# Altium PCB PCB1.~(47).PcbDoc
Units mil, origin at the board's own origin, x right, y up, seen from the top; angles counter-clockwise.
Board outline 6000 x 4000 mil, 2 copper layers (Top Layer, Bottom Layer); 38 components, 28 nets, 163 pads, 78 vias.
Unrouted connection lines stored in the file: 51.
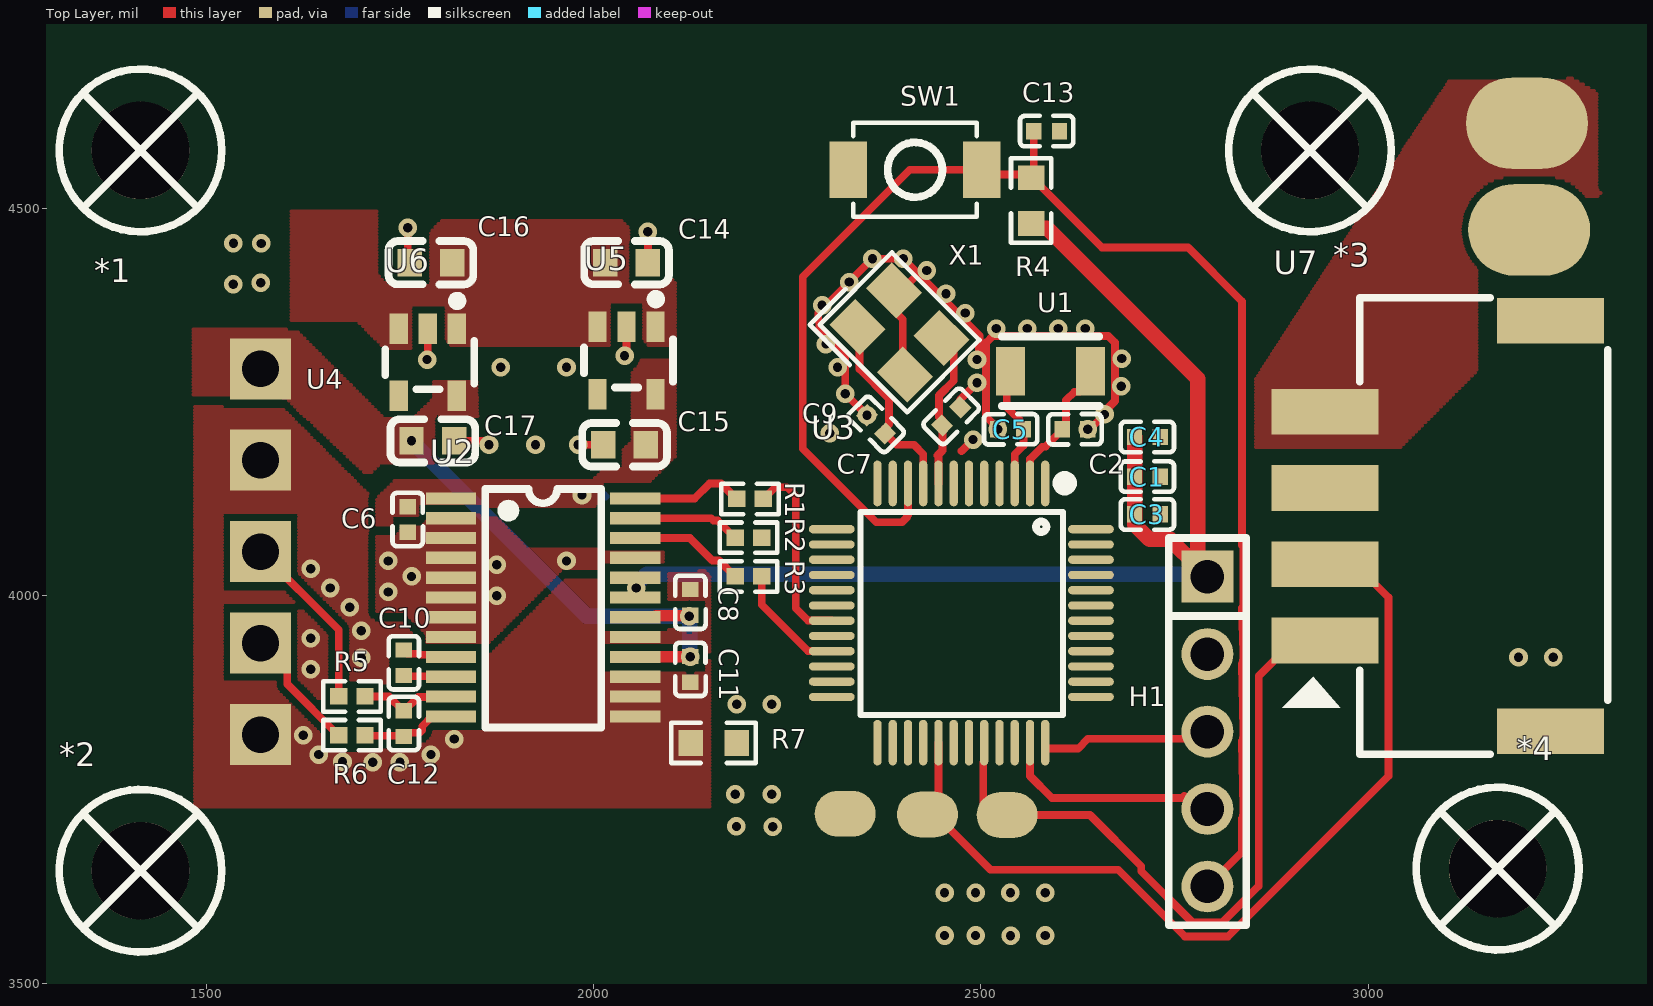
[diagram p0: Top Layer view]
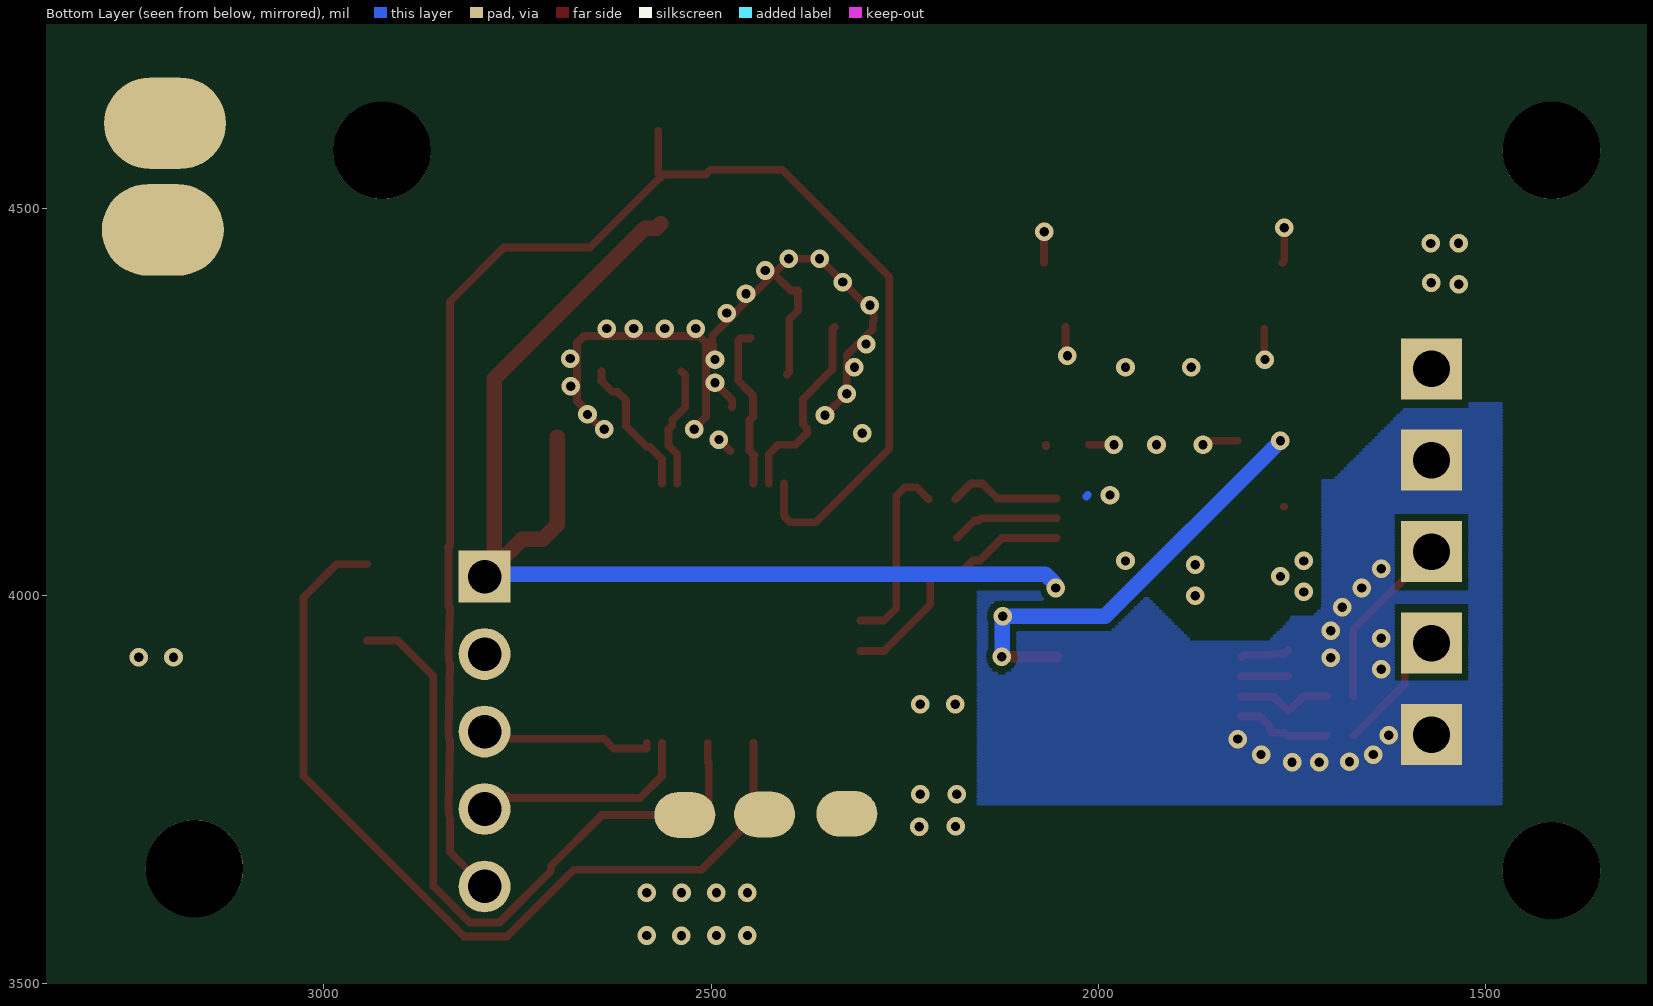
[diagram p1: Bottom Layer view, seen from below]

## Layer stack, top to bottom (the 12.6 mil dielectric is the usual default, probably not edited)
Top Solder: solder mask 0.4, Solder Resist, Dk 3.5
Top Layer: signal copper 1.4
Dielectric 1: dielectric 12.6, FR-4, Dk 4.8
Bottom Layer: signal copper 1.4
Bottom Solder: solder mask 0.4, Solder Resist, Dk 3.5

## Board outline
1000,1000 7000,1000 7000,5000 1000,5000

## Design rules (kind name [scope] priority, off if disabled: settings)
Clearance [All] p1: gap=8 ignorepadtopadclearanceinfootprint=FALSE
ComponentClearance [All] p1: gap=0 collisioncheckmode=3 verticalgap=0 showdistances=FALSE
HoleSize [All] p1: absolutevalues=TRUE maxlimit=130 minlimit=1 maxpercent=80.000 minpercent=20.000
MinimumSolderMaskSliver [All] p1: minsoldermaskwidth=4
PlaneConnect [All] p1: planeconnectstyle=Direct reliefexpansion=20 reliefentries=4 reliefconductorwidth=10 reliefairgap=10
PolygonConnect [All] p1: connectstyle=Direct reliefconductorwidth=10 reliefentries=4 polygonreliefangle="90 Angle" airgapwidth=10
RoutingVias [All] p1: holewidth=28 width=50 viastyle="Through Hole" minholewidth=28 minwidth=50 maxholewidth=28 maxwidth=50
SilkToSilkClearance [All] p1: silktosilkclearance=2
SilkToSolderMaskClearance [IsPad] p1: minsilkscreentomaskgap=2 clearancetoexposedcopper=TRUE
SolderMaskExpansion [All] p1: expansion=0 istentingtop=FALSE
SupplyNets "Schematic Supply Nets_2" [InNet('6V')] p1: voltage=0.000
SupplyNets "Schematic Supply Nets" [InNet('3V3')] p2: voltage=0.000
SupplyNets "Schematic Supply Nets_4" [InNet('5V')] p3: voltage=0.000
SupplyNets "Schematic Supply Nets_3" [InNet('DGND')] p4: voltage=0.000
SupplyNets "Schematic Supply Nets_1" [InNet('AGND')] p5: voltage=0.000
Width [All] p1: maxlimit=50 minlimit=10 preferedwidth=10
24 further rules are at their usual default settings.

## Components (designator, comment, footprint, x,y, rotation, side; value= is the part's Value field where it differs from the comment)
*1 "螺丝孔_1" M3螺丝 1415,4575 r0 top
*2 "螺丝孔_1" M3螺丝 1415,3645 r0 top
*3 "螺丝孔_1" M3螺丝 2925,4575 r0 top
*4 "螺丝孔_1" M3螺丝 3167.2,3647.74 r0 top
C1 "cc0402krx7r7bb104" C0402 2715,4153.83 r0 top value=100nF
C2 "cc0402jrnpo9bn220" C0402 2621.54,4215 r180 top value=22pF
C3 "cc0402krx7r7bb104" C0402 2715,4105 r0 top value=100nF
C4 "cc0402krx7r7bb104" C0402 2715,4205 r180 top value=100nF
C5 "cc0402jrnpo9bn220" C0402 2538.46,4215 r0 top value=22pF
C6 "cc0402krx7r7bb104" C0402 1760,4098.46 r270 top value=100nF
C7 "cc0402jrnpo9bn180" C0402 2461.7,4231.7 r45 top value=18pF
C8 "cc0402krx7r7bb104" C0402 2125,3991.54 r90 top value=100nF
C9 "cc0402jrnpo9bn180" C0402 2364.68,4221.29 r315 top value=18pF
C10 "cc0402krx7r7bb104" C0402 1755,3913.46 r90 top value=100nF
C11 "gcm155r71h103ka55d" C0402 2125,3905 r270 top value=10nF
C12 "gcm155r71h103ka55d" C0402 1755,3835 r270 top value=10nF
C13 "cc0402krx7r7bb104" C0402 2585,4600 r180 top value=100nF
C14 "cga0603x5r105k500jt" C0603 2042.56,4430 r0 top value=1uF
C15 "cga0603x5r105k500jt" C0603 2040,4195 r180 top value=1uF
C16 "cga0603x5r105k500jt" C0603 1790,4430 r180 top value=1uF
C17 "cga0603x5r105k500jt" C0603 1792.44,4200 r0 top value=1uF
H1 "pz254v-11-05p" HDR-TH_5P-P2.54-V-M 2792.56,3824.68 r270 top
R1 "frc0402f47r0ts" R0402 2202.04,4125 r0 top value=47Ω
R2 "frc0402f47r0ts" R0402 2200,4075 r0 top value=47Ω
R3 "frc0402f47r0ts" R0402 2200,4025 r0 top value=47Ω
R4 "frc0603f1002ts" R0603 2565.04,4510.31 r270 top value=10kΩ
R5 "frc0402f1000ts" R0402 1687.96,3870 r0 top value=100Ω
R6 "frc0402f1000ts" R0402 1687.96,3820 r0 top value=100Ω
R7 "0603waf0000t5e" R0603 2155,3810 r0 top value=0Ω
SW1 "ts-1088-ar02016" SW-SMD_L3.9-W3.0-P4.45 2415,4550 r0 top
U1 "fc31m2-32.768-ntlnndtl" CRYSTAL-SMD_L3.2-W1.5 2590,4290 r0 top value=32.768kHz
U2 "ads1232ipwr" TSSOP-24_L7.8-W4.4-P0.65-LS6.4-BL 1935,3985 r270 top
U3 "stm32g031c8t6" LQFP-48_L7.0-W7.0-P0.50-LS9.0-BL 2474.84,3977.68 r180 top
U4 "5个焊盘" 5个焊盘 1570,4293.1 r270 top
U5 "tps7a2033pdbvr" SOT-23-5_L2.9-W1.6-P0.95-LS2.8-BR 2042.56,4303.8 r90 top
U6 "tps7a2050pdbvr" SOT-23-5_L2.9-W1.6-P0.95-LS2.8-BR 1786.01,4301.56 r90 top
U7 "bx-xh2.54-4pwt" CONN-SMD_4P-P2.50_BX-XH2.54-4PWT 3090,4090 r90 top
X1 "x32258mob4si" CRYSTAL-SMD_4P-L3.2-W2.5-BL 2395,4340 r315 top value=8MHz

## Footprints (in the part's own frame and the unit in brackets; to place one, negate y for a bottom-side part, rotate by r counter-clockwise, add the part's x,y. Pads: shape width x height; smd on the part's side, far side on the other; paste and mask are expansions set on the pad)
5个焊盘 [mm]
  rect 2x2 hole 1.2: 1(0,0) 2(3,0) 3(6.001,0) 4(9,0) 5(12,0)
C0402 [mm]
  rect 0.5x0.54 smd: 1(-0.42,0) 2(0.42,0)
  silkscreen extent -0.87,-0.5 0.87,0.5
C0603 [mm]
  rect 0.8x0.9 smd: 1(-0.7,0) 2(0.7,0)
  silkscreen extent -1.39,-0.71 1.39,0.71
CONN-SMD_4P-P2.50_BX-XH2.54-4PWT [mm]
  rect 1.5x3.5 smd paste+0 mask+0.05: 1(-3.75,3.7) 2(-1.25,3.7) 3(1.25,3.7) 4(3.75,3.7) 5(6.73,-3.7) 6(-6.73,-3.7)
  silkscreen extent -7.49,-5.57 7.49,5.1
CRYSTAL-SMD_4P-L3.2-W2.5-BL [mm]
  rect 1.4x1.2 smd: 1(-1.1,-0.85) 2(1.1,-0.85) 3(1.1,0.85) 4(-1.1,0.85)
  silkscreen extent -2.26,-1.91 2.03,1.68
CRYSTAL-SMD_L3.2-W1.5 [mm]
  rect 0.95x1.6 smd: 1(-1.308,0) 2(1.308,0)
  silkscreen extent -1.6,-1.14 1.6,1.14
HDR-TH_5P-P2.54-V-M [mm]
  rect 1.7x1.7 hole 1.1: 1(-5.08,0)
  round 1.7 hole 1.1: 2(-2.54,0) 3(0,0) 4(2.54,0) 5(5.08,0)
  silkscreen extent -6.35,-1.27 6.35,1.27
LQFP-48_L7.0-W7.0-P0.50-LS9.0-BL [mm]
  oval 0.27x1.5 smd paste+0 mask+0.05: 1(-2.75,-4.25) 2(-2.25,-4.25) 3(-1.75,-4.25) 4(-1.25,-4.25) 5(-0.75,-4.25) 6(-0.25,-4.25) 7(0.25,-4.25) 8(0.75,-4.25) 9(1.25,-4.25) 10(1.75,-4.25) 11(2.25,-4.25) 12(2.75,-4.25) 25(2.75,4.25) 26(2.25,4.25) 27(1.75,4.25) 28(1.25,4.25) 29(0.75,4.25) 30(0.25,4.25) 31(-0.25,4.25) 32(-0.75,4.25) 33(-1.25,4.25) 34(-1.75,4.25) 35(-2.25,4.25) 36(-2.75,4.25)
  oval 1.5x0.27 smd paste+0 mask+0.05: 13(4.25,-2.75) 14(4.25,-2.25) 15(4.25,-1.75) 16(4.25,-1.25) 17(4.25,-0.75) 18(4.25,-0.25) 19(4.25,0.25) 20(4.25,0.75) 21(4.25,1.25) 22(4.25,1.75) 23(4.25,2.25) 24(4.25,2.75) 37(-4.25,2.75) 38(-4.25,2.25) 39(-4.25,1.75) 40(-4.25,1.25) 41(-4.25,0.75) 42(-4.25,0.25) 43(-4.25,-0.25) 44(-4.25,-0.75) 45(-4.25,-1.25) 46(-4.25,-1.75) 47(-4.25,-2.25) 48(-4.25,-2.75)
  silkscreen extent -3.59,-4.46 3.3,3.34
M3螺丝 [mil]
  round 126 hole 126 paste-99999 mask+4: 1(0,0)
  silkscreen extent -105,-105 105,105
R0402 [mm]
  rect 0.566x0.54 smd paste-100 mask+0.051: 1(-0.433,0) 2(0.433,0)
  silkscreen extent -0.94,-0.5 0.94,0.5
R0603 [mil]
  rect 31.75x34.02 smd paste-3937.01 mask+2: 1(-29.66,0) 2(29.66,0)
  silkscreen extent -55,-26 55,26
SOT-23-5_L2.9-W1.6-P0.95-LS2.8-BR [mm]
  rect 1x0.6 smd paste+0 mask+0.05: 1(1.1,-0.95) 2(1.1,0) 3(1.1,0.95) 4(-1.1,0.95) 5(-1.1,-0.95)
  silkscreen extent -0.89,-1.52 2.16,1.4
SW-SMD_L3.9-W3.0-P4.45 [mm]
  rect 1.23x1.86 smd: 1(-2.185,0) 2(2.185,0)
  silkscreen extent -2.03,-1.54 2.03,1.54
TSSOP-24_L7.8-W4.4-P0.65-LS6.4-BL [mm]
  rect 0.4x1.65 smd: 1(-3.575,-3.023) 2(-2.925,-3.023) 3(-2.275,-3.023) 4(-1.625,-3.023) 5(-0.975,-3.023) 6(-0.325,-3.023) 7(0.325,-3.023) 8(0.975,-3.023) 9(1.625,-3.023) 10(2.275,-3.023) 11(2.925,-3.023) 12(3.575,-3.023) 13(3.575,3.023) 14(2.925,3.023) 15(2.275,3.023) 16(1.625,3.023) 17(0.975,3.023) 18(0.325,3.023) 19(-0.325,3.023) 20(-0.975,3.023) 21(-1.625,3.023) 22(-2.275,3.023) 23(-2.925,3.023) 24(-3.575,3.023)
  silkscreen extent -3.89,-1.91 3.94,1.9

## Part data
C1 C3 C4 C6 C8 C10 C13: "容值:100nF;精度:±10%;额定电压:16V;温度系数:X7R;", JLCPCB Part Class="Extended Part", LCSC Part Name="100nF ±10% 16V", Manufacturer=YAGEO(国巨), ManufacturerPart=CC0402KRX7R7BB104, Temperature Coefficient=X7R, Tolerance=±10%, Voltage Rating=16V
C2 C5: "容值:22pF;精度:±5%;额定电压:50V;温度系数:NP0;", JLCPCB Part Class="Extended Part", LCSC Part Name="22pF ±5% 50V", Manufacturer=YAGEO(国巨), ManufacturerPart=CC0402JRNPO9BN220, Temperature Coefficient=NP0, Tolerance=±5%, Voltage Rating=50V
C7 C9: "容值:18pF;精度:±5%;额定电压:50V;温度系数:NP0;", JLCPCB Part Class="Extended Part", LCSC Part Name="18pF ±5% 50V", Manufacturer=YAGEO(国巨), ManufacturerPart=CC0402JRNPO9BN180, Temperature Coefficient=NP0, Tolerance=±5%, Voltage Rating=50V
C11 C12: "容值:10nF;精度:±10%;额定电压:50V;温度系数:X7R;", JLCPCB Part Class="Extended Part", LCSC Part Name="10nF ±10% 50V", Manufacturer=muRata(村田), ManufacturerPart=GCM155R71H103KA55D, Temperature Coefficient=X7R, Tolerance=±10%, Voltage Rating=50V
C14 C15 C16 C17: "容值:1uF;精度:±10%;额定电压:50V;温度系数:X5R;", JLCPCB Part Class="Extended Part", LCSC Part Name="1uF ±10% 50V 停产", Manufacturer=HRE(芯声), ManufacturerPart=CGA0603X5R105K500JT, Temperature Coefficient=X5R, Tolerance=±10%, Voltage Rating=50V
H1: "插针结构:1x5P;间距:2.54mm;行距:-;圆针/方针:方针;安装方式:直插;排数:单排;总PIN位数:5P;额定电流:3A;额定电压:250V;配合针长度:6mm;塑高:2.5mm;端接针长度:3mm;触头材质:黄铜;触头镀层:-;工作温度:-40℃~+105℃;颜色:黑色;", Color=黑色, Current Rating=3A, JLCPCB Part Class="Extended Part", LCSC Part Name="1x5P 间距:2.54mm 方针 直插", Manufacturer=XFCN(兴飞), ManufacturerPart=PZ254V-11-05P, Operating Temperature=-40℃~+105℃, Voltage Rating (Max)=250V
R1 R2 R3: "电阻类型:厚膜电阻;阻值:47Ω;精度:±1%;功率:62.5mW;工作电压:50V;温度系数:±100ppm/℃;", JLCPCB Part Class="Extended Part", LCSC Part Name="47Ω ±1% 62.5mW 厚膜电阻", Manufacturer=FOJAN(富捷), ManufacturerPart=FRC0402F47R0TS, Operating Temperature=-55℃~+155℃, Power(Watts)=62.5mW, Temperature Coefficient=±100ppm/℃, Tolerance=±1%, Voltage-Supply(Max)=50V
R4: "电阻类型:厚膜电阻;阻值:10kΩ;精度:±1%;功率:100mW;工作电压:75V;温度系数:±100ppm/℃;", JLCPCB Part Class="Extended Part", LCSC Part Name="10kΩ ±1% 100mW 厚膜电阻", Manufacturer=FOJAN(富捷), ManufacturerPart=FRC0603F1002TS, Operating Temperature=-55℃~+155℃, Power(Watts)=100mW, Temperature Coefficient=±100ppm/℃, Tolerance=±1%, Voltage-Supply(Max)=75V
R5 R6: "电阻类型:厚膜电阻;阻值:100Ω;精度:±1%;功率:62.5mW;工作电压:50V;温度系数:±100ppm/℃;", JLCPCB Part Class="Extended Part", LCSC Part Name="100Ω ±1% 62.5mW 厚膜电阻", Manufacturer=FOJAN(富捷), ManufacturerPart=FRC0402F1000TS, Operating Temperature=-55℃~+155℃, Power(Watts)=62.5mW, Temperature Coefficient=±100ppm/℃, Tolerance=±1%, Voltage-Supply(Max)=50V
R7: "电阻类型:厚膜电阻;阻值:0Ω;精度:±1%;功率:100mW;工作电压:75V;温度系数:-;", JLCPCB Part Class="Basic Part", LCSC Part Name="0Ω ±1% 100mW 厚膜电阻", Manufacturer=UNI-ROYAL(厚声), ManufacturerPart=0603WAF0000T5E, Operating Temperature=-55℃~+155℃, Power(Watts)=100mW, Temperature Coefficient=-, Tolerance=±1%, Voltage-Supply(Max)=75V
SW1: "电路结构:单刀单掷;按钮形状:圆形按钮;作用力:1.6N;安装方式:立贴;开关长度:3.9mm;开关宽度:3mm;开关高度:2mm;带支架:不带支架;触点电流:50mA;额定电压:12V;带灯:-;工作寿命:10万次;", Actuator/Cap Color=黑色, Contact Current=50mA, IP Rating=-, JLCPCB Part Class="Basic Part", LCSC Part Name="3.9*3*2mm 立贴 轻触开关", Manufacturer=XUNPU(讯普), ManufacturerPart=TS-1088-AR02016, Operating Force=1.6N, Operating Temperature=-30℃~+80℃, Voltage Rating=12V
U1: "晶振类型:贴片晶振;频率:32.768kHz;常温频差:±10ppm;负载电容:12.5pF;频率稳定度:±10ppm;", Equivalent Series Resistance(ESR)=70kΩ, Frequency Stability=±10ppm, JLCPCB Part Class="Extended Part", LCSC Part Name="3215 2P 32.768kHz 12.5pF ±10ppm -40~+85℃(±10ppm)", Load Capacitance=12.5pF, Manufacturer=HCI(杭晶), ManufacturerPart=FC31M2-32.768-NTLNNDTL, Operating Temperature=-40℃~+85℃
U2: "分辨率(位):24;采样率:10Hz;工作电压:2.7V~5.3V;接口类型:SPI;", Clock Frequency=4.9152MHz；200kHz~8MHz, JLCPCB Part Class="Extended Part", LCSC Part Name="用于桥式传感器的24bit 模数转换器", Manufacturer=TI(德州仪器), ManufacturerPart=ADS1232IPWR, Operating Temperature=-40℃~+105℃, Quiescent Current (Iq)=1.3uA, Temperature Sensors=内置, Voltage - Supply=2.7V~5.3V, Voltage Reference=外置, Voltage Reference Drift=-
U3: "CPU内核:ARM Cortex-M0+;CPU最大主频:64MHz;CPU位数:32 Bit;", JLCPCB Part Class="Extended Part", LCSC Part Name="主流Arm Cortex-M0+ MCU，具有64 KB Flash存储器、8 KB RAM、64 MHz CPU、2x USART、定时器、ADC和通信接口，1.7-3.6V", Manufacturer=ST(意法半导体), ManufacturerPart=STM32G031C8T6, Operating Temperature=-40℃~+85℃, Voltage - Supply=1.7V~3.6V
U5: "输出类型:固定;最大输入电压:6V;输出电压:3.3V;输出电流:300mA;输出极性:正极;", Dropout Voltage=140mV@(300mA), JLCPCB Part Class="Extended Part", LCSC Part Name="具有高 PSRR 的 300mA、超低噪声、低 IQ、低压降 (LDO) 线性稳压器", Manufacturer=TI(德州仪器), ManufacturerPart=TPS7A2033PDBVR, Maximum Input Voltage=6V, Operating Temperature=-40℃~+125℃@(Tj), Output Current=300mA, Output Voltage=3.3V, standby current=15uA
U6: "输出极性:正极;工作电压:6V;输出电压:5V;输出电流:300mA;电源纹波抑制比(PSRR):65dB@(100Hz);输出类型:固定;", JLCPCB Part Class="Extended Part", LCSC Part Name="800mV~5.5V 300mA 6V", Manufacturer=TI(德州仪器), ManufacturerPart=TPS7A2050PDBVR, Operating Temperature=-40℃~+125℃@(Tj), Output Current=300mA, Output Voltage=5V, Power Supply Rejection Ratio (PSRR)=65dB@(100Hz), standby current=6.5uA, Voltage - Supply=6V, Voltage Dropout=140mV@(300mA)
U7: "插针结构:1x4P;间距:2.5mm;安装方式:卧贴;参考系列:XH;总PIN数:4P;排数:1;每排PIN数:4;行距:-;额定电流:3A;触头材质:黄铜;触头镀层:锡;工作温度:-25℃~+85℃;", Color=米色, Current Rating=3A, Flame Retardant Rating=-, JLCPCB Part Class="Extended Part", LCSC Part Name="1x4P 间距:2.5mm 卧贴 系列:XH", Manufacturer=Bossie(博锡), ManufacturerPart=BX-XH2.54-4PWT, Operating Temperature=-25℃~+85℃, Voltage Rating=250V
X1: "晶振类型:贴片晶振;频率:8MHz;常温频差:±10ppm;负载电容:12pF;频率稳定度:±20ppm;", Equivalent Series Resistance(ESR)=180Ω, Frequency Stability=±20ppm, JLCPCB Part Class="Extended Part", LCSC Part Name="YSX321SL 8MHZ 4P 3225 12PF ±10PPM -40~85℃ (±20PPM)", Load Capacitance=12pF, Manufacturer=YXC(扬兴晶振), ManufacturerPart=X32258MOB4SI, Normal temperature Frequency Tolerance=±10ppm, Operating Temperature=-40℃~+85℃

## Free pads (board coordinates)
  oval 78.74x59.06 all layers, no hole: 7(2324.75,3718.52) 7(2431.17,3717.65) 7(2533.87,3716.95)
  oval 157.48x118.11 all layers, no hole: 7(3205,4610) 7(3208.05,4472.38)

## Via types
v1: diameter 24, hole 12, Top Layer to Bottom Layer, tented both sides, 78 vias

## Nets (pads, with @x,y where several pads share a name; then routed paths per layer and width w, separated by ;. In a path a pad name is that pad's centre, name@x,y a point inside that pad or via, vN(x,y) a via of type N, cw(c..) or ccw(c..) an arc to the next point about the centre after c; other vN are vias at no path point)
3V3: C1.1 C3.1 C4.2 C6.1 C15.1 H1.1 R4.2 U2.1 U2.19 U2.20 U3.4 U3.5 U3.6 U5.5 | length 1532.9
  Top Layer w10: C6.1 C6.1@1760.79,4115 ; C15.1@2067.56,4193.03 C15.1
  Top Layer w20: R4.2 2570.92,4474.77 2585.41,4474.77 2780.25,4279.94 H1.1@2780.25,4036.99 ; C4.2@2698.46,4204.53 C4.2 C3.1 2698.62,4104.84 2698.62,4091.99 2717.84,4072.77 2744.47,4072.77 H1.1@2780.25,4036.99 ; H1.1 H1.1@2780.25,4036.99
  Bottom Layer w10: v1@1983.6,4128.6 v1(1985,4130) ; 2013.74,4130 2015.53,4128.21
  Bottom Layer w20: v1(2055,4010) 2055.77,4010.77 2055.77,4015.1 2068.72,4028.05 2789.19,4028.05 H1.1
5V: C8.1 C11.1 C17.1 U2.16 U2.18 U4.1 U6.5 | length 649.2
  Top Layer w10: v1(2123.61,3973.61) C8.1 ; v1(2124.74,3921.28) C11.1
  Top Layer w15: U2.16 2054.26,3921.28 v1(2124.74,3921.28) ; U2.18 2078.61,3972.21 2080.81,3974.42 2122.79,3974.42 v1(2123.61,3973.61)
  Bottom Layer w10: v1(2123.61,3973.61) v1@2124.17,3973.04 ; v1@2124.17,3921.85 v1(2124.74,3921.28)
  Bottom Layer w20: v1(1765,4200) 1991.39,3973.61 v1(2123.61,3973.61) ; v1@2124.17,3921.85 v1@2124.17,3973.04
6V: C14.1 C16.1 pad.7@3205,4610 U5.1 U5.3 U6.1 U6.3 U7.4
AGND: C8.2 C11.2 R7.1 U2.13 U2.14 U2.15 U2.17 U4.2 U4.5
  other v1: 1715,3785 1750,3785 1675.87,3785.63 1645,3795 1790,3795 1820,3815 1625,3820 1635,3905 1700,3920 1635,3945 1700,3955 1685,3985 1660,4010 1635,4035
AINN1: R6.1 U4.4 | length 160.9
  Top Layer w10: U4.4 1604.37,3904.39 1604.37,3886.04 1670.41,3820 R6.1
AINP1: R5.1 U4.3 | length 228.7
  Top Layer w10: U4.3 1670.92,3955.94 R5.1
DGND: C1.2 C2.1 C3.2 C4.1 C5.1 C6.2 C7.2 C9.1 C13.1 C14.2 C15.2 C16.2 C17.2 H1.2 pad.7@2324.75,3718.52 pad.7@3208.05,4472.38 R7.2 SW1.1 U2.2 U2.3 U2.4 U2.5 U2.6 U2.7 U2.8 U2.21 U3.7 U5.2 U6.2 U7.3 U7.5 U7.6 X1.2 X1.4 | length 1352.5
  Top Layer w10: v1(1760,4475) 1760,4432.44 C16.2 ; v1(1785,4305) 1786.02,4306.02 U6.2 ; C17.2 1856.21,4200 1861.21,4195 v1(1865,4195) ; v1(1980,4195) C15.2 ; v1(2040,4310) 2042.57,4312.56 U5.2 ; v1(2070,4470) 2070.12,4469.88 C14.2 ; v1(2352.98,4232.98) v1(2325,4260.96) 2325,4310.88 2291.52,4344.36 2291.52,4353.48 2290,4355 2290,4365 v1(2360,4435) v1(2400,4435) v1@2419.14,4415.86 ; X1.2 2399.18,4288.5 2399.18,4356.81 2388.04,4367.95 X1.4 2397.57,4394.29 v1@2419.14,4415.86 ; C7.2 2472.83,4243.95 2472.83,4250.8 2473.39,4251.35 2473.39,4253.39 v1(2495,4275) ; v1(2495,4305) 2497.68,4307.68 2497.68,4324.07 2498.48,4324.87 2498.48,4335.64 2467.06,4367.06 2467.06,4367.94 v1@2419.14,4415.86 ; v1(2521.92,4215) 2521.92,4215.79 2506.8,4230.91 2506.8,4326.88 2515.36,4335.44 2664.64,4335.44 2673.2,4326.88 v1@2673.2,4306.26 ; v1(2638.08,4215) 2642.92,4219.84 C2.1@2642.92,4220.63 ; C2.1@2638.08,4215.79 C2.1@2642.92,4220.63 ; v1(2681.38,4270.61) v1@2673.2,4270.61 ; v1(2681.94,4306.26) v1@2673.2,4306.26 ; C2.1@2642.92,4220.63 2646.22,4220.63 v1(2659.71,4234.12) 2659.71,4237.91 2673.2,4251.4 v1@2673.2,4270.61 ; v1@2673.2,4270.61 v1@2673.2,4306.26
  other v1: 2453.19,3561.4 2493.19,3561.4 2538.44,3560.94 2583.19,3561.4 2453.19,3616.4 2493.19,3616.4 2538.19,3616.4 2583.19,3616.4 2184.44,3702.22 2231.16,3701.9 2182.87,3743.61 2229.91,3743.61 2185,3860 2230,3860 3194.27,3920.47 3239.27,3920.47 1875,4000 1735,4005 1765,4025 1875,4040 1735,4045 1965,4045 1925,4195 2305,4210 1880,4295 1965,4295 2315,4295 2300,4325 2520,4345 2560,4345 2600,4345 2635,4345 2480,4365 2295,4375 2455,4390 1534.72,4402.35 1570.25,4404.08 2330,4405 2430,4420 1535,4455 1570.83,4454.92
DOUT: R1.2 U3.19 | length 251.1
  Top Layer w10: R1.2 2219.59,4125 2234.58,4140 2250.22,4140 2261.09,4129.12 2261.09,3983.84 2276.97,3967.96 2307.4,3967.96 U3.19
NetC2_2: C2.2 U1.2 U3.2 | length 183.5
  Top Layer w10: U3.2 2563.54,4145.12 2563.54,4176.49 2579.61,4192.56 2583.35,4192.56 2609.84,4219.06 2609.84,4252.3 2621.05,4263.5 2627.8,4263.5 2641.5,4277.21 U1.2
NetC5_2: C5.2 U1.1 U3.3 | length 160.6
  Top Layer w10: U1.1 2533.5,4285 2533.5,4243.5 2550.16,4226.85 2550.16,4219.84 C5.2 2555,4193.85 2543.86,4182.71 2543.86,4145.12 U3.3
NetC7_1: C7.1 U3.8 X1.3 | length 214.9
  Top Layer w10: U3.8 U3.8 2445.35,4152.44 2445.35,4179.95 2444.11,4181.19 2450.56,4187.63 2450.56,4226.29 2445.91,4230.93 2445.91,4258.56 2465.11,4277.75 2465.11,4329.54 2462.33,4332.33 2450,4332.33 X1.3
NetC9_2: C9.2 U3.9 X1.1 | length 254.5
  Top Layer w10: X1.1 2343.5,4344.18 2343.5,4292.39 2381.34,4254.54 2381.34,4221.41 2376.37,4216.44 C9.2 2391.12,4194.85 2413.69,4194.85 2425.67,4182.86 2425.67,4152.44 2425.67,4145.04 U3.9
NetC10_1: C10.1 U2.10 | length 61.6
  Top Layer w10: C10.1 1755.74,3896.18 1815.25,3896.18 U2.10
NetC10_2: C10.2 U2.9 | length 64.7
  Top Layer w10: C10.2 1759.84,3925.16 1774.84,3925.16 1776.11,3923.89 1813.13,3923.89 U2.9
NetC12_1: C12.1 R5.2 U2.11 | length 126.2
  Top Layer w10: R5.2 1735.75,3870 1754.21,3851.54 C12.1 1755.79,3851.54 1773.52,3869.27 1815.43,3869.27 U2.11
NetC12_2: C12.2 R6.2 U2.12 | length 125.3
  Top Layer w10: R6.2 1705.77,3819.23 1754.23,3819.23 C12.2 1759.84,3823.3 1775.44,3823.3 1778.63,3826.5 1778.63,3831.5 1791.39,3844.26 U2.12
NetR1_1: R1.1 U2.24 | length 147.3
  Top Layer w10: U2.24 2130.54,4125.74 2149.8,4145 2164.49,4145 2184.49,4125 R1.1
NetR2_1: R2.1 U2.23 | length 139.4
  Top Layer w10: U2.23 2151.82,4100.15 2154.94,4097.03 2160.42,4097.03 2182.45,4075 R2.1
NetR3_1: R3.1 U2.22 | length 149.5
  Top Layer w10: U2.22 2124.37,4074.56 2153.42,4045.51 2161.94,4045.51 2182.45,4025 R3.1
NRST: C13.2 H1.5 R4.1 SW1.2 U3.10 | length 2000.2
  Top Layer w10: U3.10 2406.06,4144.88 2406.06,4104.31 2406.1,4104.27 2404.62,4102.79 2404.62,4101.29 2398.25,4094.91 2365.11,4094.91 2270,4190.02 2270,4411.81 2408.19,4550 SW1.2 ; R4.1 2565.25,4539.76 R4.1@2566.38,4539.76 ; C13.2 2568.46,4545.99 R4.1@2566.38,4543.91 ; H1.5 2837.36,3669.49 2837.36,3712.38 ccw(c2792.56,3724.68) 2839.01,3725.57 2837.36,3812.38 ccw(c2792.56,3824.68) 2839.01,3825.57 2837.36,3912.38 ccw(c2792.56,3924.68) 2839,3925.99 2837.36,3984.18 2839.02,3985.83 2839.02,4063.53 2837.36,4065.19 2837.36,4379.89 2834.43,4382.82 2767.43,4449.82 2656.33,4449.82 R4.1@2566.38,4539.76 ; SW1.2 SW1.2@2507.11,4543.91 ; SW1.2 SW1.2@2507.11,4543.91 ; SW1.2 SW1.2@2507.11,4543.91 ; SW1.2 SW1.2@2507.11,4543.91 ; SW1.2@2507.11,4543.91 R4.1@2566.38,4543.91 ; R4.1@2566.38,4539.76 R4.1@2566.38,4543.91
PDWN: R3.2 U3.21 | length 151.8
  Top Layer w10: R3.2 2217.04,3988.52 2276.97,3928.59 2307.4,3928.59 U3.21
SCLK: R2.2 U3.20
SWCLK: H1.3 U3.36 | length 226.1
  Top Layer w10: U3.36 2583.11,3802.84 2583.27,3802.68 2625.54,3802.68 2638.27,3815.4 2783.27,3815.4 H1.3
SWDIO: H1.4 U3.35 | length 291.8
  Top Layer w10: U3.35 2563.54,3810.24 2563.54,3767.32 2591.81,3739.05 2760.32,3739.05 2762.78,3741.51 2779.61,3724.68 H1.4
USART1_RX: pad.7@2533.87,3716.95 U3.32 U7.1 | length 899.6
  Top Layer w10: U3.32 2504.37,3785.98 2503.13,3784.73 2503.13,3731.39 2515.38,3719.15 2531.67,3719.15 pad.7@2533.87,3716.95 ; pad.7@2531.67,3716.95 2640.92,3716.95 2707.11,3650.75 2707.11,3644.42 2773.31,3578.22 2811.8,3578.22 2858.98,3625.4 2858.98,3896.39 2904.96,3942.36 U7.1
USART1_TX: pad.7@2431.17,3717.65 U3.29 U7.2 | length 1175
  Top Layer w10: pad.7@2431.17,3717.65 2441.17,3717.65 2512.41,3646.41 2677.23,3646.41 2763.42,3560.22 2819.26,3560.22 3026.23,3767.19 3026.23,3998.26 2983.7,4040.78 U7.2 ; pad.7@2431.45,3717.65 2445.31,3731.51 U3.29
USART2_RX: U3.14
USART2_TX: U3.13
pads on no net: *1.1 *2.1 *3.1 *4.1 U3.1 U3.11 U3.12 U3.15 U3.16 U3.17 U3.18 U3.22 U3.23 U3.24 U3.25 U3.26 U3.27 U3.28 U3.30 U3.31 U3.33 U3.34 U3.37 U3.38 U3.39 U3.40 U3.41 U3.42 U3.43 U3.44 U3.45 U3.46 U3.47 U3.48 U5.4 U6.4
copper on no net: | length 24.3
  Top Layer w10: 2475.16,4186.85 v1(2490,4201.69) v1@2490,4205

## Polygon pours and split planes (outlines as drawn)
6V on Top Layer "NONET_L-01_P-001" (hatched Horizontal grid 4 track 5, remove dead copper, pour order 17): 3260,4670 3255,4665 3105,4665 3055,4590 2855,4280 2855,4190 3040,4190 3140,4290 3140,4515 3295,4515 3300,4520 3295,4525 3295,4650
DGND on Top Layer "NONET_L-01_P-001" (hatched Horizontal grid 4 track 5, remove dead copper, pour order 15): 1389.4,3473.32 1389.4,2330.12 3114.4,2330.12 3114.4,3466.93
5V on Top Layer "NONET_L-01_P-001" (hatched Horizontal grid 4 track 5, remove dead copper, pour order 9): 1848.57,4280 1828.57,4280 1793.57,4280 1793.57,4255 1773.57,4235 1723.57,4235 1613.57,4345 1483.57,4345 1483.57,4255 1600,4255 1635,4225 1708.57,4155 1723.57,4170 1793.57,4170 1793.57,4230 1798.57,4235 1803.57,4230 1850,4230
AGND on Top Layer "NONET_L-01_P-001" (hatched Horizontal grid 4 track 5, remove dead copper, pour order 7): 1520,4245 1595,4245 1710,4130 1710,3975 1750,3975 1782.5,3942.5 1862.5,3942.5 1870,3935 1965,4030 2135,4030 2140,4035 2150,4025 2150,3725 2135,3725 2115,3725 1485,3725 1485,4245
DGND on Top Layer "NONET_L-01_P-001" (hatched Horizontal grid 4 track 5, remove dead copper, pour order 5): 1720,4090 1775,4090 1787.5,4102.5 1785,4105 1785,4115 1860,4115 1915,4060 2090,4060 2090,4040 2085,4035 1960,4035 1860,3935 1785,3935 1785,3950 1755,3980 1720,3980
6V on Top Layer "NONET_L-01_P-001" (hatched Horizontal grid 4 track 5, remove dead copper, pour order 3): 1610,4500 1610,4355 1695,4355 1735,4315 1740,4320 1765,4320 1765,4365 1775,4375 1810,4375 1810,4330 1820,4320 2025,4320 2025,4375 2030,4380 2060,4380 2060,4335 2075,4320 2105,4320 2105,4405 2095,4415 2045,4415 2045,4475 2035,4485 1805,4485 1790,4470 1790,4400 1735,4400 1720,4415 1720,4500
3V3 on Top Layer "NONET_L-01_P-001" (hatched Horizontal grid 4 track 5, remove dead copper, pour order 2): 2050,4305 2050,4200 2000,4150 1745,4150 1720,4125 1720,4090 1775,4090 1800,4115 2000,4115 2025,4140 2065,4140 2105,4180 2105,4295 2095,4305
DGND on Bottom Layer "NONET_L-01_P-001" (hatched Horizontal grid 4 track 5, remove dead copper, pour order 16): 3114.4,3473.32 3114.4,2325.12 1389.4,2325.12 1389.4,3466.93
AGND on Bottom Layer "NONET_L-01_P-001" (hatched Horizontal grid 4 track 5, remove dead copper, pour order 12): 1480,4250 1595,4250 1695,4150 1710,4150 1710,3985 1720,3975 1750,3975 1750,3970 1780,3940 1880,3940 1980,4040 2135,4040 2160,4015 2155,4010 2155,3730 1480,3730

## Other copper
Top Layer:
  pour cut-out: 2285,4375 2360,4450 2360,4455 2400,4455 2495,4360 2495,4355 2505,4345 2520,4360 2640.08,4360 2675,4325.08 2675,4230 2640,4195 2500,4195 2455,4240 2425,4210 2345,4210 2305,4250 2310,4255 2310,4300 2275,4335 2280,4340 2280,4380

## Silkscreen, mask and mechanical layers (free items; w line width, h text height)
Mechanical 1:
  lines w10: 1295,3530 3325,3530 3325,4685 1295,4685 1295,3530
